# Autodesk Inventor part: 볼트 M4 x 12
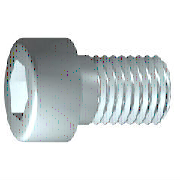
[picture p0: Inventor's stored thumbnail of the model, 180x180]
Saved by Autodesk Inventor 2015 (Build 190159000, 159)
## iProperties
IsCustomPart: 0
Created: 2012-02
Part Number: 볼트 M4 x 12
Material: 스테인리스강
Description: 6각 소켓 머리 캡 나사
Document SubType Name: Modeling
Standard: ISO 4762
Designer: mduedu
Standard Revision: Fourth edition 2004-03-01
Standards Organization: ISO
Language: ko-KR
Size Designation: M4 x 12
Categories: <MemberInstance><Categories><Category DisplayName="조임쇠" InternalName="e4da775c-781d-43d5-af7c-5136215cf5a6" Mnemonic="FSTN"><Category DisplayName="볼트" InternalN
Density: 8.08 g/cm^3
Appearance: 반광택
Author: mduedu
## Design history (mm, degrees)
sketch "스케치1"
  geometry: L1 (-1, 0)-(12, 0); L2 (12, 0)-(12, 2); L3 (12, 2)-(1.75, 2); L4 (1.75, 2)-(1.32, 2); L5 (1.32, 2)-(0, 2); L6 (0, 2)-(0, 3.5); L7 (0, 3.5)-(-4, 3.5); L8 (-4, 3.5)-(-4, 1.732); L9 (-4, 1.732)-(-2, 1.732); L10 (-2, 1.732)-(-1, 0); L11 (-7.2, 0)-(15.2, 0) reference; L12 (0, -0.7)-(0, 4.2) reference; L13 (1.75, 2)-(0, 2)
  constraints: 22 end point, 6 parallel, 2 collinear, 2 perpendicular, 1 horizontal, 1 point on line
  dimensions: "d1" = 10.25 distance from line of L3.end L2 (= GEL); "d2" = 0.42952 distance of L4.end L3.end (computed from GAL); "d3" = 4 distance between parallel lines of L8 L6 (= KOH); "d4" = 2 distance of L8.end L9.end (= INTI); "d5" = 60 deg angle of L10 L1; "d6" = 4 diameter of L3 L1 (= GD); "d7" = 4 diameter of L5 L1 (= BDM); "d8" = 3.4641 diameter of L9 L1 (= 1.1547 x SW); "d9" = 7 diameter of L7 L1 (= KOD); "d26" = 12 distance between parallel lines of L12 L2 (= NLG)
revolve "본체" sketch "스케치1" stored, may be unused: angle "d10" = 90 deg
sketch "스케치2"
  geometry: L1 (0, -4.9)-(0, 4.9) reference; L2 (-4.9, 0)-(4.9, 0) reference; L3 (1.732, 0)-(0.866, -1.5); L4 (0.866, -1.5)-(-0.866, -1.5); L5 (-0.866, -1.5)-(-1.732, 0); L6 (-1.732, 0)-(-0.866, 1.5); L7 (-0.866, 1.5)-(0.866, 1.5); L8 (0.866, 1.5)-(1.732, 0); 2 further points
  constraints: 12 end point, 1 coincident, 1 horizontal alignment, 1 point on line, 12 other
extrude "슬롯" join sketch "스케치2" stored distance "d11" = 10; taper "d12" = 0 deg
workplane "Work Plane1"
fillet "Fillet2" dims "d30" = 0.1 (= R)
body "Solid1"
fillet "모깎기1" dims "d17" = 0.4 (= RR)
feature "스레드" dims "d13" = 10.25 (= GEL), "d14" = 0
chamfer "모따기1" distance "d15" = 0.42941 (= -0.5 x SPD + 0.5 x GD); stored, may be unused: second distance "d16" = 0.42941 (= GUL), angle "d27" = 45 deg
other parameters: "GD" = 4 [user parameter; used in 2 equation terms], "NLG" = 12 [user parameter; used in 1 equation term], "GEL" = 10.25 [user parameter; used in 2 equation terms], "KOD" = 7 [user parameter; used in 1 equation term], "KOH" = 4 [user parameter; used in 1 equation term], "INTI" = 2 [user parameter; used in 1 equation term], "GAL" = 0.42941 (= 0.61345 x PTC) [user parameter; used in 1 equation term], "GUL" = 0.42941 (= 0.61345 x PTC) [user parameter; used in 1 equation term], "BDM" = 4 (= NND) [user parameter; used in 1 equation term], "SW" = 3 [user parameter; used in 2 equation terms], "RR" = 0.4 [user parameter; used in 1 equation term], "SPD" = 3.14117 (= NND - 1.2269 x PTC) [user parameter; used in 1 equation term], "d19" = 0, "d28" = 0, "d29" = 0, "R" = 0.1 [user parameter; used in 1 equation term], "TOA" = 30 deg [user parameter], "GD1" = 3.14117 (= THREADDIA - 1.2269 x PTC) [user parameter], "THREADDIA" = 4 [user parameter; used in 1 equation term], "FAWI" = 45 deg [user parameter], "TPU" = 14.28571 (computed from PTC) [user parameter], "PTC" = 0.7 [user parameter; used in 5 equation terms], "NND" = 4 [user parameter; used in 2 equation terms], "E0" = 3.465 (= 1.155 x SW) [user parameter]
